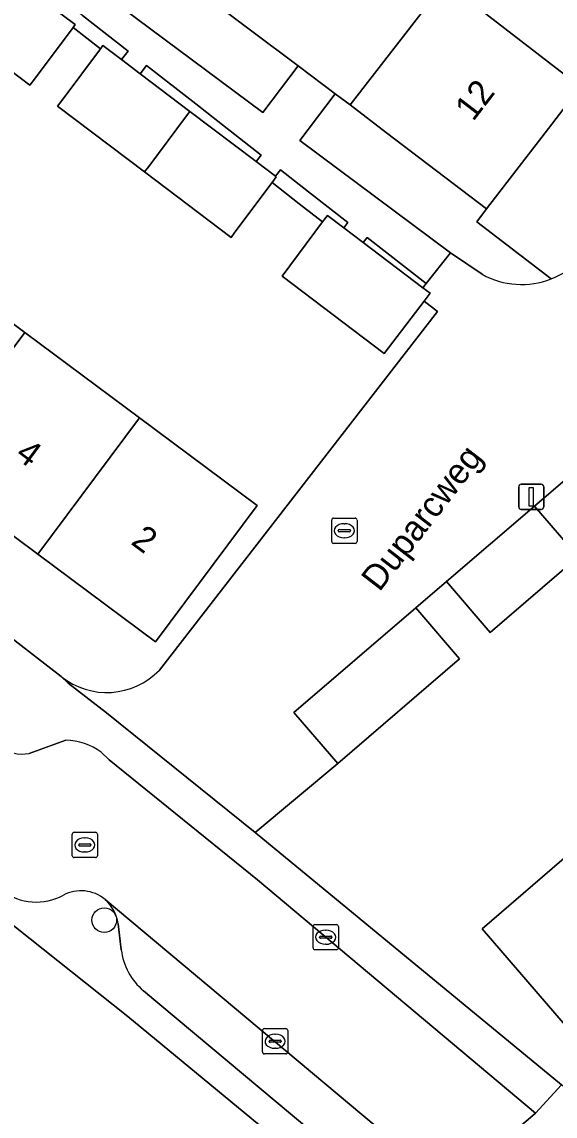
# Model space of a CAD drawing. Extents: x 159039 to 160102, y 381214 to 382524.
# Drawn here: x 159220.65 to 159241.77, y 381461.02 to 381504.4 of the extents above; entities that cross this region are included whole.
import ezdxf

# ---------------------------------------------------------------- set-up
doc = ezdxf.new("R2010")
doc.units = 0
for name, color, linetype in [('IMGEO_Boom', 7, 'Continuous'), ('IMGEO_Erf', 7, 'Continuous'), ('IMGEO_Groenvoorziening', 7, 'Continuous'), ('IMGEO_Kolk', 7, 'Continuous'), ('IMGEO_Lichtmast', 7, 'Continuous'), ('IMGEO_Openbare_ruimte_label', 7, 'Continuous'), ('IMGEO_Pand', 7, 'Continuous'), ('IMGEO_Pand_nummerreeks', 7, 'Continuous'), ('IMGEO_Parkeervlak_open', 7, 'Continuous'), ('IMGEO_Rijbaan_lokaal_open', 7, 'Continuous'), ('IMGEO_Rioolput', 7, 'Continuous'), ('IMGEO_Voetpad_open', 7, 'Continuous')]:
    doc.layers.add(name, color=color, linetype=linetype)

msp = doc.modelspace()

# ---------------------------------------------------------------- linework, layer by layer
at = {"layer": 'IMGEO_Boom'}
msp.add_circle((159223.914, 381468.787), 0.489, dxfattribs=at)
at = {"layer": 'IMGEO_Erf'}
for points in [[(159256.666, 381530.894), (159261.984, 381526.784), (159258.103, 381521.74), (159254.425, 381516.96), (159250.601, 381511.99), (159246.679, 381506.893), (159242.785, 381501.832), (159241.375, 381500), (159239.061, 381496.992), (159238.669, 381496.482), (159241.619, 381494.213)], [(159232.559, 381496.471), (159231.636, 381497.192), (159230.56, 381498.032), (159229.092, 381496.063), (159228.937, 381495.854), (159225.509, 381498.452), (159222.066, 381501.061), (159222.241, 381501.296), (159223.764, 381503.337), (159222.679, 381504.184), (159221.149, 381502.131), (159220.97, 381501.891), (159216.745, 381505.093), (159218.518, 381507.433), (159215.703, 381509.632), (159210.768, 381503.013), (159203.221, 381492.897), (159214.857, 381484.15), (159222.203, 381478.451)], [(159224.253, 381508.179), (159231.589, 381502.66), (159233.059, 381501.554), (159233.651, 381501.109), (159237.416, 381505.981)], [(159226.096, 381478.704), (159237.113, 381492.916), (159236.581, 381493.332), (159235.007, 381491.255), (159230.957, 381494.323), (159232.559, 381496.471)], [(159242.688, 381483.191), (159239.206, 381480.195), (159237.468, 381482.214), (159236.25, 381481.168), (159237.989, 381479.148), (159233.165, 381474.998), (159229.894, 381472.262), (159242.021, 381462.254)], [(159230.287, 381460.476), (159224.852, 381464.969), (159215.929, 381472.046), (159213.988, 381469.989), (159215.902, 381468.183), (159212.73, 381464.819), (159210.815, 381466.625), (159210.558, 381466.352), (159209.733, 381465.477), (159211.647, 381463.672), (159207.265, 381459.025), (159203.889, 381455.445), (159201.975, 381457.25), (159201.159, 381456.385), (159199.738, 381454.878), (159201.652, 381453.073), (159198.653, 381449.893), (159195.501, 381446.549)]]:
    msp.add_lwpolyline(points, dxfattribs=at)
for points in [[(159220.765, 381492.089), (159225.306, 381488.703), (159229.965, 381485.23), (159225.939, 381479.828), (159221.279, 381483.302), (159216.738, 381486.688), (159212.171, 381490.092), (159207.764, 381493.378), (159209.47, 381495.665), (159213.455, 381501.009), (159214.809, 381500), (159217.862, 381497.724), (159216.198, 381495.493), (159216.296, 381495.42)], [(159253.199, 381480.765), (159257.861, 381484.775), (159262.748, 381488.98), (159267.348, 381492.937), (159271.706, 381487.872), (159267.108, 381483.916), (159262.221, 381479.712), (159257.559, 381475.702), (159252.721, 381471.54), (159248.022, 381467.498), (159243.238, 381463.382), (159238.88, 381468.447), (159243.662, 381472.561), (159248.361, 381476.603)]]:
    msp.add_lwpolyline(points, close=True, dxfattribs=at)
for centre, radius, start, end in [((159240.442, 381497.22), 3.23, 291.3735, 316.0986), ((159224.012, 381480.696), 2.883, 231.1385, 316.2981)]:
    msp.add_arc(centre, radius, start, end, dxfattribs=at)
at = {"layer": 'IMGEO_Groenvoorziening'}
for points in [[(159224.253, 381508.179), (159222.161, 381509.796), (159220.696, 381507.9), (159230.193, 381500.805), (159231.589, 381502.66)], [(159223.048, 381504.657), (159222.031, 381505.451), (159221.736, 381505.073), (159222.762, 381504.295), (159222.679, 381504.184), (159223.764, 381503.337), (159223.859, 381503.465), (159224.594, 381502.908), (159224.857, 381503.245)], [(159227.539, 381501.152), (159225.593, 381502.671), (159225.338, 381502.344), (159227.302, 381500.856), (159229.93, 381498.864), (159230.134, 381499.125), (159228.408, 381500.473)], [(159232.005, 381497.665), (159230.89, 381498.536), (159230.694, 381498.285), (159230.729, 381498.259), (159230.56, 381498.032), (159231.636, 381497.192), (159232.559, 381496.471), (159232.75, 381496.727), (159233.397, 381496.237), (159233.563, 381496.449)], [(159234.322, 381495.856), (159234.165, 381495.655), (159236.532, 381493.861), (159236.663, 381494.028)]]:
    msp.add_lwpolyline(points, close=True, dxfattribs=at)
for points in [[(159235.088, 381500), (159233.651, 381501.109), (159233.059, 381501.554), (159231.667, 381499.704), (159237.625, 381495.253), (159238.878, 381494.395)], [(159241.619, 381494.213), (159238.669, 381496.482), (159239.061, 381496.992), (159235.088, 381500)]]:
    msp.add_lwpolyline(points, dxfattribs=at)
msp.add_arc((159240.442, 381497.22), 3.229, 241.0275, 291.3748, dxfattribs=at)
at = {"layer": 'IMGEO_Kolk'}
for p, q in [((159232.999, 381484.727), (159233.851, 381484.727)), ((159232.924, 381483.801), (159232.924, 381484.653)), ((159233.412, 381484.507), (159233.437, 381484.507)), ((159233.925, 381484.653), (159233.925, 381483.801)), ((159233.183, 381484.221), (159233.183, 381484.233)), ((159233.621, 381484.184), (159233.223, 381484.184)), ((159233.226, 381484.27), (159233.624, 381484.27)), ((159233.435, 381483.947), (159233.41, 381483.947)), ((159233.667, 381484.233), (159233.667, 381484.221)), ((159233.851, 381483.727), (159232.999, 381483.727)), ((159230.181, 381463.559), (159230.181, 381464.411)), ((159230.256, 381464.485), (159231.108, 381464.485)), ((159231.182, 381464.411), (159231.182, 381463.559)), ((159230.44, 381463.979), (159230.44, 381463.991)), ((159230.878, 381463.942), (159230.48, 381463.942)), ((159230.483, 381464.028), (159230.881, 381464.028)), ((159230.669, 381464.265), (159230.694, 381464.265)), ((159230.924, 381463.991), (159230.924, 381463.979)), ((159231.108, 381463.485), (159230.256, 381463.485)), ((159230.692, 381463.705), (159230.667, 381463.705))]:
    msp.add_line(p, q, dxfattribs=at)
for points in [[(159232.999, 381484.727), (159233.851, 381484.727)], [(159232.924, 381483.801), (159232.924, 381484.653)], [(159233.925, 381484.653), (159233.925, 381483.801)], [(159233.851, 381483.727), (159232.999, 381483.727)], [(159230.181, 381463.559), (159230.181, 381464.411)], [(159230.256, 381464.485), (159231.108, 381464.485)], [(159231.182, 381464.411), (159231.182, 381463.559)], [(159231.108, 381463.485), (159230.256, 381463.485)]]:
    msp.add_lwpolyline(points, dxfattribs=at)
for centre, radius, start, end in [((159233.001, 381484.651), 0.0765, 91.552, 178.448), ((159233.001, 381484.651), 0.0765, 91.552, 178.448), ((159233.849, 381484.651), 0.0765, 1.552, 88.448), ((159233.849, 381484.651), 0.0765, 1.552, 88.448), ((159233.223, 381484.23), 0.0403, 85.8775, 175.7526), ((159233.22, 381484.22), 0.0366, 178.938, 274.7102), ((159233.624, 381484.227), 0.043, 264.8664, 352.4533), ((159233.628, 381484.232), 0.0386, 1.7309, 96.639), ((159233.001, 381483.803), 0.0765, 181.552, 268.448), ((159233.001, 381483.803), 0.0765, 181.552, 268.448), ((159233.849, 381483.803), 0.0765, 271.552, 358.448), ((159233.849, 381483.803), 0.0765, 271.552, 358.448), ((159230.258, 381464.409), 0.0765, 91.552, 178.448), ((159230.258, 381464.409), 0.0765, 91.552, 178.448), ((159231.106, 381464.409), 0.0765, 1.552, 88.448), ((159231.106, 381464.409), 0.0765, 1.552, 88.448), ((159230.48, 381463.988), 0.0403, 85.8775, 175.7526), ((159230.477, 381463.978), 0.0366, 178.938, 274.7102), ((159230.881, 381463.985), 0.043, 264.8664, 352.4533), ((159230.885, 381463.99), 0.0386, 1.7309, 96.639), ((159230.258, 381463.561), 0.0765, 181.552, 268.448), ((159230.258, 381463.561), 0.0765, 181.552, 268.448), ((159231.106, 381463.561), 0.0765, 271.552, 358.448), ((159231.106, 381463.561), 0.0765, 271.552, 358.448)]:
    msp.add_arc(centre, radius, start, end, dxfattribs=at)
for centre, major_axis, ratio, start_param, end_param in [((159233.411, 381484.227), (-0.387, 0.002), 0.722429, 4.712389, 7.853982), ((159233.436, 381484.227), (-0.39, 0.002), 0.717154, 1.570796, 4.712389), ((159230.668, 381463.985), (-0.387, 0.002), 0.722429, 4.712389, 7.853982), ((159230.693, 381463.985), (-0.39, 0.002), 0.717154, 1.570796, 4.712389)]:
    msp.add_ellipse(centre, major_axis=major_axis, ratio=ratio, start_param=start_param, end_param=end_param, dxfattribs=at)
at = {"layer": 'IMGEO_Lichtmast'}
for p, q in [((159240.43, 381486.071), (159241.22, 381486.071)), ((159241.22, 381486.071), (159240.43, 381486.071)), ((159240.33, 381485.171), (159240.33, 381485.971)), ((159240.33, 381485.971), (159240.33, 381485.171)), ((159241.32, 381485.971), (159241.32, 381485.171)), ((159241.32, 381485.171), (159241.32, 381485.971)), ((159241.22, 381485.071), (159240.43, 381485.071)), ((159240.43, 381485.071), (159241.22, 381485.071))]:
    msp.add_line(p, q, dxfattribs=at)
msp.add_lwpolyline([(159240.75, 381485.946), (159240.9, 381485.946), (159240.9, 381485.196), (159240.75, 381485.196), (159240.75, 381485.946)], dxfattribs=at)
for centre, start, end in [((159240.43, 381485.971), 90, 180), ((159240.43, 381485.971), 90, 180), ((159241.22, 381485.971), 0, 90), ((159241.22, 381485.971), 360, 90), ((159240.43, 381485.171), 180, 270), ((159240.43, 381485.171), 180, 270), ((159241.22, 381485.171), 270, 0), ((159241.22, 381485.171), 270, 0)]:
    msp.add_arc(centre, 0.1, start, end, dxfattribs=at)
at = {"layer": 'IMGEO_Pand'}
for points in [[(159246.679, 381506.893), (159241.32, 381511.034), (159237.416, 381505.981), (159242.785, 381501.832)], [(159220.944, 381505.673), (159218.556, 381507.483), (159218.518, 381507.433), (159216.745, 381505.093), (159220.97, 381501.891), (159221.149, 381502.131), (159222.679, 381504.184), (159222.762, 381504.295), (159221.736, 381505.073)], [(159237.416, 381505.981), (159233.651, 381501.109), (159235.088, 381500), (159239.061, 381496.992), (159241.375, 381500), (159242.785, 381501.832)], [(159225.338, 381502.344), (159224.594, 381502.908), (159223.859, 381503.465), (159223.764, 381503.337), (159222.241, 381501.296), (159222.066, 381501.061), (159225.509, 381498.452), (159225.674, 381498.674), (159227.17, 381500.679), (159227.302, 381500.856)], [(159229.93, 381498.864), (159227.302, 381500.856), (159227.17, 381500.679), (159225.674, 381498.674), (159225.509, 381498.452), (159228.937, 381495.854), (159229.092, 381496.063), (159230.56, 381498.032), (159230.729, 381498.259), (159230.694, 381498.285)], [(159234.165, 381495.655), (159233.397, 381496.237), (159232.75, 381496.727), (159232.559, 381496.471), (159230.957, 381494.323), (159235.007, 381491.255), (159236.581, 381493.332), (159236.818, 381493.645), (159236.532, 381493.861)], [(159216.296, 381495.42), (159216.198, 381495.493), (159212.171, 381490.092), (159216.738, 381486.688), (159220.765, 381492.089)], [(159225.306, 381488.703), (159220.765, 381492.089), (159216.738, 381486.688), (159221.279, 381483.302)], [(159225.306, 381488.703), (159221.279, 381483.302), (159225.939, 381479.828), (159229.965, 381485.23)], [(159244.398, 381488.166), (159240.952, 381485.206), (159242.688, 381483.191), (159246.131, 381486.153)], [(159242.688, 381483.191), (159240.952, 381485.206), (159237.468, 381482.214), (159239.206, 381480.195)], [(159236.25, 381481.168), (159231.424, 381477.022), (159233.165, 381474.998), (159237.989, 381479.148)], [(159243.662, 381472.561), (159238.88, 381468.447), (159243.238, 381463.382), (159248.022, 381467.498)]]:
    msp.add_lwpolyline(points, close=True, dxfattribs=at)
at = {"layer": 'IMGEO_Parkeervlak_open'}
for points in [[(159234.68, 381458.877), (159236.456, 381458.88), (159236.718, 381458.893), (159223.947, 381469.609)], [(159224.468, 381468.644), (159224.588, 381467.614)], [(159225.466, 381465.988), (159233.393, 381459.344)]]:
    msp.add_lwpolyline(points, dxfattribs=at)
for centre, radius, start, end in [((159222.837, 381468.387), 1.651, 8.9627, 47.7662), ((159227.069, 381467.904), 2.498, 186.6574, 230.0785)]:
    msp.add_arc(centre, radius, start, end, dxfattribs=at)
at = {"layer": 'IMGEO_Rijbaan_lokaal_open'}
for points in [[(159222.391, 381475.922), (159220.939, 381475.397)], [(159223.947, 381469.609), (159236.718, 381458.893), (159237.003, 381458.717), (159237.602, 381458.234), (159239.301, 381459.685), (159240.999, 381461.135), (159229.98, 381470.382), (159224.113, 381475.149), (159223.785, 381475.443)]]:
    msp.add_lwpolyline(points, dxfattribs=at)
for centre, radius, start, end in [((159220.668, 381476.796), 1.425, 229.2167, 280.968), ((159222.337, 381473.496), 2.426, 53.3543, 88.7187), ((159221.226, 381471.751), 2.247, 232.7304, 298.3675), ((159222.997, 381468.463), 1.488, 50.3485, 118.2578)]:
    msp.add_arc(centre, radius, start, end, dxfattribs=at)
at = {"layer": 'IMGEO_Rioolput'}
for p, q in [((159222.642, 381471.343), (159222.642, 381472.195)), ((159222.717, 381472.269), (159223.569, 381472.269)), ((159223.643, 381472.195), (159223.643, 381471.343)), ((159222.901, 381471.763), (159222.901, 381471.775)), ((159223.339, 381471.726), (159222.941, 381471.726)), ((159222.944, 381471.812), (159223.342, 381471.812)), ((159223.13, 381472.049), (159223.155, 381472.049)), ((159223.385, 381471.775), (159223.385, 381471.763)), ((159223.153, 381471.489), (159223.128, 381471.489)), ((159223.569, 381471.269), (159222.717, 381471.269)), ((159232.185, 381467.685), (159232.185, 381468.537)), ((159232.26, 381468.611), (159233.112, 381468.611)), ((159232.673, 381468.391), (159232.698, 381468.391)), ((159233.186, 381468.537), (159233.186, 381467.685)), ((159232.444, 381468.105), (159232.444, 381468.117)), ((159232.882, 381468.068), (159232.484, 381468.068)), ((159232.487, 381468.154), (159232.885, 381468.154)), ((159232.696, 381467.831), (159232.671, 381467.831)), ((159232.928, 381468.117), (159232.928, 381468.105)), ((159233.112, 381467.611), (159232.26, 381467.611))]:
    msp.add_line(p, q, dxfattribs=at)
for points in [[(159222.642, 381471.343), (159222.642, 381472.195)], [(159222.717, 381472.269), (159223.569, 381472.269)], [(159223.643, 381472.195), (159223.643, 381471.343)], [(159223.569, 381471.269), (159222.717, 381471.269)], [(159232.185, 381467.685), (159232.185, 381468.537)], [(159232.26, 381468.611), (159233.112, 381468.611)], [(159233.186, 381468.537), (159233.186, 381467.685)], [(159233.112, 381467.611), (159232.26, 381467.611)]]:
    msp.add_lwpolyline(points, dxfattribs=at)
for centre, radius, start, end in [((159222.719, 381472.193), 0.0765, 91.552, 178.448), ((159222.719, 381472.193), 0.0765, 91.552, 178.448), ((159223.567, 381472.193), 0.0765, 1.552, 88.448), ((159223.567, 381472.193), 0.0765, 1.552, 88.448), ((159222.941, 381471.772), 0.0403, 85.8775, 175.7526), ((159222.938, 381471.762), 0.0366, 178.938, 274.7102), ((159223.342, 381471.769), 0.043, 264.8664, 352.4533), ((159223.346, 381471.774), 0.0386, 1.7309, 96.639), ((159222.719, 381471.345), 0.0765, 181.552, 268.448), ((159222.719, 381471.345), 0.0765, 181.552, 268.448), ((159223.567, 381471.345), 0.0765, 271.552, 358.448), ((159223.567, 381471.345), 0.0765, 271.552, 358.448), ((159232.262, 381468.535), 0.0765, 91.552, 178.448), ((159232.262, 381468.535), 0.0765, 91.552, 178.448), ((159233.11, 381468.535), 0.0765, 1.552, 88.448), ((159233.11, 381468.535), 0.0765, 1.552, 88.448), ((159232.484, 381468.114), 0.0403, 85.8775, 175.7526), ((159232.481, 381468.104), 0.0366, 178.938, 274.7102), ((159232.885, 381468.111), 0.043, 264.8664, 352.4533), ((159232.889, 381468.116), 0.0386, 1.7309, 96.639), ((159232.262, 381467.687), 0.0765, 181.552, 268.448), ((159232.262, 381467.687), 0.0765, 181.552, 268.448), ((159233.11, 381467.687), 0.0765, 271.552, 358.448), ((159233.11, 381467.687), 0.0765, 271.552, 358.448)]:
    msp.add_arc(centre, radius, start, end, dxfattribs=at)
for centre, major_axis, ratio, start_param, end_param in [((159223.129, 381471.769), (-0.387, 0.002), 0.722429, 4.712389, 7.853982), ((159223.154, 381471.769), (-0.39, 0.002), 0.717154, 1.570796, 4.712389), ((159232.672, 381468.111), (-0.387, 0.002), 0.722429, 4.712389, 7.853982), ((159232.697, 381468.111), (-0.39, 0.002), 0.717154, 1.570796, 4.712389)]:
    msp.add_ellipse(centre, major_axis=major_axis, ratio=ratio, start_param=start_param, end_param=end_param, dxfattribs=at)
at = {"layer": 'IMGEO_Voetpad_open'}
for points in [[(159222.203, 381478.451), (159214.857, 381484.15), (159203.221, 381492.897), (159201.517, 381494.178), (159193.333, 381500), (159192.473, 381500.612), (159191.957, 381501.003), (159191.931, 381501.023), (159191.012, 381504.016), (159191.482, 381504.708), (159193.761, 381507.875), (159191.91, 381509.302), (159191.13, 381509.922), (159185.68, 381503.207), (159190.18, 381500), (159191.411, 381499.122), (159197.785, 381494.58)], [(159223.048, 381504.657), (159224.857, 381503.245), (159224.594, 381502.908), (159225.338, 381502.344), (159225.593, 381502.671), (159227.539, 381501.152), (159228.408, 381500.473), (159230.134, 381499.125), (159229.93, 381498.864), (159230.694, 381498.285), (159230.89, 381498.536), (159232.005, 381497.665), (159233.563, 381496.449), (159233.397, 381496.237), (159234.165, 381495.655), (159234.322, 381495.856), (159236.663, 381494.028), (159237.625, 381495.253), (159231.667, 381499.704), (159233.059, 381501.554), (159231.589, 381502.66), (159230.193, 381500.805), (159220.696, 381507.9)], [(159222.203, 381478.451), (159222.481, 381478.188), (159224.002, 381477.003), (159229.894, 381472.262), (159233.165, 381474.998), (159231.424, 381477.022), (159236.25, 381481.168), (159237.468, 381482.214), (159240.952, 381485.206), (159244.398, 381488.166), (159245.794, 381489.364), (159246.799, 381490.227), (159250.458, 381493.371), (159254.2, 381496.585), (159255.35, 381497.573), (159256.608, 381498.653)], [(159183.894, 381495.608), (159188.166, 381492.633), (159193.646, 381488.84), (159204.436, 381481.087), (159204.968, 381480.705), (159207.389, 381478.814), (159208.94, 381477.591), (159214.514, 381473.169), (159215.929, 381472.046), (159224.852, 381464.969), (159230.287, 381460.476), (159234.904, 381456.013), (159235.658, 381456.67), (159235.712, 381456.713), (159237.602, 381458.234), (159237.003, 381458.717), (159236.718, 381458.893), (159236.456, 381458.88), (159234.68, 381458.877)], [(159238.878, 381494.395), (159237.625, 381495.253), (159236.663, 381494.028), (159236.532, 381493.861), (159236.818, 381493.645), (159236.581, 381493.332), (159237.113, 381492.916), (159226.096, 381478.704)], [(159223.785, 381475.443), (159224.113, 381475.149), (159229.98, 381470.382), (159240.999, 381461.135), (159242.021, 381462.254), (159229.894, 381472.262), (159224.002, 381477.003), (159222.481, 381478.188), (159222.203, 381478.451)], [(159220.939, 381475.397), (159222.391, 381475.922)], [(159224.588, 381467.614), (159224.468, 381468.644)], [(159233.393, 381459.344), (159225.466, 381465.988)], [(159242.669, 381461.719), (159242.021, 381462.254), (159240.999, 381461.135), (159239.301, 381459.685), (159237.602, 381458.234), (159235.712, 381456.713)]]:
    msp.add_lwpolyline(points, dxfattribs=at)
for centre, radius, start, end in [((159240.442, 381497.22), 3.23, 291.3735, 316.0986), ((159240.442, 381497.22), 3.229, 241.0275, 291.3748), ((159224.012, 381480.696), 2.883, 231.1385, 316.2981), ((159220.668, 381476.796), 1.425, 229.2167, 280.968), ((159222.337, 381473.496), 2.426, 53.3543, 88.7187), ((159221.226, 381471.751), 2.247, 232.7304, 298.3675), ((159222.997, 381468.463), 1.488, 50.3485, 118.2578), ((159222.837, 381468.387), 1.651, 8.9627, 47.7662), ((159227.069, 381467.904), 2.498, 186.6574, 230.0785)]:
    msp.add_arc(centre, radius, start, end, dxfattribs=at)

# ---------------------------------------------------------------- texts
at = {"layer": 'IMGEO_Openbare_ruimte_label'}
msp.add_text('Duparcweg', height=1, rotation=52.3161, dxfattribs=at).set_placement((159234.812, 381481.772))
at = {"layer": 'IMGEO_Pand_nummerreeks'}
for s, rotation, p in [('12', 52.4241, (159238.524, 381500.426)), ('4', 323.2944, (159220.341, 381487.145)), ('2', 323.2944, (159224.928, 381483.725))]:
    msp.add_text(s, height=1, rotation=rotation, dxfattribs=at).set_placement(p)

doc.saveas('drawing.dxf')
